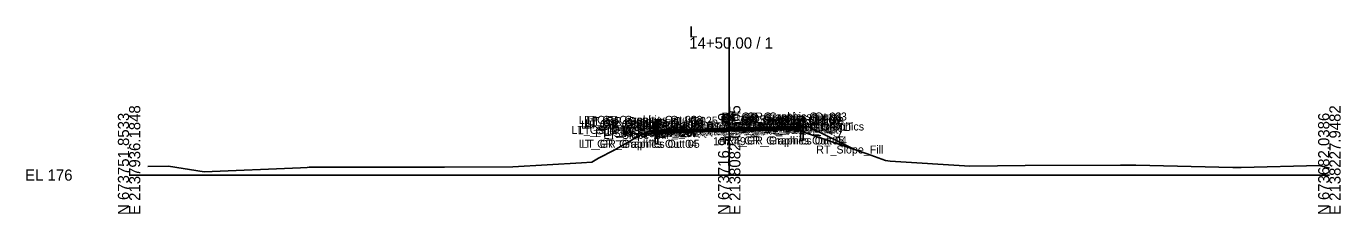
# Model space of a CAD drawing. Extents: x -26 to 5503, y -10 to 7033.
# Drawn here: x -25.7 to 302.8, y 5490.3 to 5537.3 of the extents above; entities that cross this region are included whole.
import ezdxf

# ---------------------------------------------------------------- set-up
doc = ezdxf.new("R2010")
doc.units = 0
for name, color, linetype in [('Default', 7, 'Continuous'), ('Exist Cross Section Cell', 7, 'Continuous'), ('Exist XS Center Line Elevation Label', 7, 'Continuous'), ('Exist XS Ground Line', 7, 'Continuous'), ('Prop CMT Guardrail Graphics', 7, 'Continuous'), ('Prop CMT Pvmt Course 1', 7, 'Continuous'), ('Prop CMT Pvmt Course 2', 7, 'Continuous'), ('Prop CMT Pvmt Course 3', 7, 'Continuous'), ('Prop CMT Pvmt Surface', 7, 'Continuous'), ('Prop CMT Pvmt Surface Overlay', 7, 'Continuous'), ('Prop CMT Pvmt Surface Shoulder', 7, 'Continuous'), ('Prop CMT Shld Paved Course 1', 7, 'Continuous'), ('Prop CMT Shld Paved Course 2', 7, 'Continuous'), ('Prop CMT Shld Paved Course 3', 7, 'Continuous'), ('Prop CMT Slope Grass', 7, 'Continuous'), ('Prop CMT Subgrade Earthwork', 7, 'Continuous'), ('Prop XS Earthwork Shape', 7, 'Continuous'), ('Prop XS EOT Tick Mark', 7, 'Continuous'), ('Prop XS SE Text', 7, 'Continuous'), ('Prop XS Side Slope Text', 7, 'Continuous')]:
    doc.layers.add(name, color=color, linetype=linetype)

msp = doc.modelspace()

# ---------------------------------------------------------------- linework, layer by layer
at = {"layer": 'Exist Cross Section Cell'}
for p, q in [((150, 5500), (150, 5534.48)), ((0, 5500), (150, 5500)), ((150, 5500), (300, 5500))]:
    msp.add_line(p, q, dxfattribs=at)
at = {"layer": 'Exist XS Ground Line'}
for p, q in [((121.21, 5506.22), (127.74, 5510)), ((127.74, 5510), (131.37, 5510.75)), ((131.37, 5510.75), (137.66, 5511.28)), ((137.66, 5511.28), (145.24, 5511.41)), ((145.24, 5511.41), (149.33, 5511.49)), ((149.33, 5511.49), (150, 5511.49)), ((150, 5511.49), (158.78, 5511.41)), ((158.78, 5511.41), (162.52, 5511.36)), ((162.52, 5511.36), (165.67, 5511.3)), ((165.67, 5511.3), (167.13, 5511.17)), ((167.13, 5511.17), (169.29, 5510.49)), ((169.29, 5510.49), (184.45, 5505.31)), ((117.35, 5504.23), (121.21, 5506.22)), ((95.92, 5502.03), (113.04, 5503.04)), ((113.04, 5503.04), (115.67, 5503.24)), ((115.67, 5503.24), (117.35, 5504.23)), ((184.45, 5505.31), (189.09, 5503.61)), ((189.09, 5503.61), (190.27, 5503.5)), ((190.27, 5503.5), (210.12, 5502.2)), ((4.7, 5502.18), (9.89, 5502.25)), ((9.89, 5502.25), (18.8, 5500.85)), ((18.8, 5500.85), (42.82, 5501.84)), ((42.82, 5501.84), (44.51, 5501.92)), ((44.51, 5501.92), (45.04, 5501.94)), ((45.04, 5501.94), (70.21, 5501.94)), ((70.21, 5501.94), (78.83, 5501.99)), ((78.83, 5501.99), (95.92, 5502.03)), ((210.12, 5502.2), (223.93, 5502.36)), ((223.93, 5502.36), (247.79, 5502.47)), ((247.79, 5502.47), (250.15, 5502.46)), ((250.15, 5502.46), (251.6, 5502.47)), ((251.6, 5502.47), (275.86, 5501.93)), ((275.86, 5501.93), (277.95, 5501.91)), ((277.95, 5501.91), (297.54, 5502.4)), ((297.54, 5502.4), (300, 5501.76))]:
    msp.add_line(p, q, dxfattribs=at)
at = {"layer": 'Prop CMT Guardrail Graphics'}
for points in [[(131.48, 5507.83), (131.48, 5513.83)], [(131.48, 5513.83), (132.81, 5513.83), (133.08, 5513.53)], [(133.08, 5512.95), (132.81, 5512.66), (132.15, 5512.66)], [(133.08, 5513.53), (132.81, 5513.24)], [(132.81, 5513.24), (133.08, 5512.95)], [(168.52, 5514.67), (167.19, 5514.67), (166.92, 5514.38)], [(166.92, 5514.38), (167.19, 5514.09)], [(167.19, 5514.09), (166.92, 5513.8)], [(166.92, 5513.8), (167.19, 5513.5), (167.85, 5513.5)], [(167.85, 5513.5), (167.85, 5508.67)], [(168.52, 5508.67), (168.52, 5514.67)], [(132.15, 5512.66), (132.15, 5507.83)], [(132.15, 5507.83), (131.48, 5507.83)], [(167.85, 5508.67), (168.52, 5508.67)]]:
    msp.add_lwpolyline(points, dxfattribs=at)
at = {"layer": 'Prop CMT Pvmt Course 1'}
for points in [[(150, 5511.75), (138, 5511.45)], [(138, 5511.2), (150, 5511.5)], [(138, 5511.45), (138, 5511.2)], [(150, 5511.75), (162, 5512.05)], [(162, 5511.8), (150, 5511.5)], [(150, 5511.62), (150, 5511.75)], [(150, 5511.62), (150, 5511.75)], [(150, 5511.5), (150, 5511.62), (150, 5511.62)], [(150, 5511.5), (150, 5511.62), (150, 5511.62)], [(162, 5512.05), (162, 5511.8)]]:
    msp.add_lwpolyline(points, dxfattribs=at)
at = {"layer": 'Prop CMT Pvmt Course 2'}
for points in [[(150, 5511.5), (138, 5511.2)], [(138, 5510.99), (150, 5511.29)], [(138, 5511.2), (138, 5510.99)], [(150, 5511.5), (162, 5511.8)], [(162, 5511.59), (150, 5511.29)], [(150, 5511.29), (150, 5511.5)], [(150, 5511.29), (150, 5511.5)], [(162, 5511.8), (162, 5511.59)]]:
    msp.add_lwpolyline(points, dxfattribs=at)
at = {"layer": 'Prop CMT Pvmt Course 3'}
for points in [[(150, 5511.29), (138, 5510.99)], [(138, 5510.99), (138, 5510.66)], [(138, 5510.66), (150, 5510.96)], [(150, 5511.29), (162, 5511.59)], [(150, 5510.96), (150, 5511.29)], [(150, 5510.96), (150, 5511.29)], [(162, 5511.26), (150, 5510.96)], [(162, 5511.59), (162, 5511.26)]]:
    msp.add_lwpolyline(points, dxfattribs=at)
at = {"layer": 'Prop CMT Pvmt Surface'}
for points in [[(150, 5511.75), (138, 5511.45)], [(150, 5511.75), (162, 5512.05)]]:
    msp.add_lwpolyline(points, dxfattribs=at)
at = {"layer": 'Prop CMT Pvmt Surface Overlay'}
for points in [[(150, 5511.75), (138, 5511.45)], [(150, 5511.75), (162, 5512.05)]]:
    msp.add_lwpolyline(points, dxfattribs=at)
at = {"layer": 'Prop CMT Pvmt Surface Shoulder'}
for points in [[(138, 5511.45), (133.09, 5511.33)], [(162, 5512.05), (166.91, 5512.17)]]:
    msp.add_lwpolyline(points, dxfattribs=at)
at = {"layer": 'Prop CMT Shld Paved Course 1'}
for points in [[(138, 5511.45), (133.09, 5511.33), (132.84, 5511.07)], [(132.84, 5511.07), (138, 5511.2)], [(138, 5511.2), (138, 5511.45)], [(162, 5512.05), (166.91, 5512.17), (167.15, 5511.93)], [(162, 5511.8), (162, 5512.05)], [(167.15, 5511.93), (162, 5511.8)]]:
    msp.add_lwpolyline(points, dxfattribs=at)
at = {"layer": 'Prop CMT Shld Paved Course 2'}
for points in [[(138, 5511.2), (132.84, 5511.07), (132.62, 5510.86)], [(132.62, 5510.86), (138, 5510.99)], [(138, 5510.99), (138, 5511.2)], [(162, 5511.8), (167.15, 5511.93), (167.35, 5511.72)], [(162, 5511.59), (162, 5511.8)], [(167.35, 5511.72), (162, 5511.59)]]:
    msp.add_lwpolyline(points, dxfattribs=at)
at = {"layer": 'Prop CMT Shld Paved Course 3'}
for points in [[(132.62, 5510.86), (132.28, 5510.51)], [(132.28, 5510.51), (138, 5510.66)], [(138, 5510.99), (132.62, 5510.86)], [(132.62, 5510.86), (132.62, 5510.86)], [(138, 5510.66), (138, 5510.99)], [(162, 5511.59), (167.35, 5511.72)], [(162, 5511.26), (162, 5511.59)], [(167.68, 5511.4), (162, 5511.26)], [(167.35, 5511.72), (167.35, 5511.72)], [(167.35, 5511.72), (167.68, 5511.4)]]:
    msp.add_lwpolyline(points, dxfattribs=at)
at = {"layer": 'Prop CMT Slope Grass'}
for points in [[(130.08, 5511.09), (128.04, 5510.07)], [(133.08, 5511.33), (130.08, 5511.09)], [(133.09, 5511.33), (133.08, 5511.33)], [(166.91, 5512.17), (166.92, 5512.17)], [(166.92, 5512.17), (169.92, 5512.07)], [(169.92, 5512.07), (181.28, 5506.4)]]:
    msp.add_lwpolyline(points, dxfattribs=at)
at = {"layer": 'Prop CMT Subgrade Earthwork'}
for points in [[(132.28, 5510.51), (131.59, 5511.21)], [(138, 5510.66), (132.28, 5510.51)], [(150, 5510.96), (138, 5510.66)], [(150, 5510.96), (162, 5511.26)], [(162, 5511.26), (167.68, 5511.4)], [(167.68, 5511.4), (168.4, 5512.12)]]:
    msp.add_lwpolyline(points, dxfattribs=at)
at = {"layer": 'Prop XS Earthwork Shape'}
for points in [[(131.99, 5510.81), (131.59, 5511.21), (130.08, 5511.09), (128.04, 5510.07), (131.37, 5510.75)], [(131.99, 5510.81), (137.66, 5511.28), (145.24, 5511.41), (149.33, 5511.49), (150, 5511.49), (158.78, 5511.41), (162.52, 5511.36), (164.57, 5511.32), (162, 5511.26), (150, 5510.96), (138, 5510.66), (132.28, 5510.51)], [(164.57, 5511.32), (165.67, 5511.3), (167.13, 5511.17), (169.29, 5510.49), (181.28, 5506.4), (169.92, 5512.07), (168.4, 5512.12), (167.68, 5511.4)]]:
    msp.add_lwpolyline(points, close=True, dxfattribs=at)
at = {"layer": 'Prop XS EOT Tick Mark'}
for points in [[(162, 5512.05), (162, 5513.05)], [(138, 5511.45), (138, 5512.45)]]:
    msp.add_lwpolyline(points, dxfattribs=at)

# ---------------------------------------------------------------- texts
at = {"layer": 'Default'}
for s, height, p in [('LT_GR_Graphics Out 03', 2, (112.38, 5512.83)), ('LT_GR_Graphics Out 06', 2, (113, 5511.66)), ('LT_GR_Graphics Out 02', 2, (113.71, 5512.83)), ('LT_GR_Graphics Out 09', 2, (113.71, 5512.24)), ('LT_GR_Graphics Out 07', 2, (113.71, 5511.66)), ('LT_GR_Graphics Out 08', 2, (113.98, 5511.95)), ('LT_GR_Graphics Out 01', 2, (114.55, 5512.53)), ('LT_TM_OEOT', 2, (128.94, 5511.45)), ('RT_GS_OS_GR_Face_Graphics', 2, (144.33, 5511.17)), ('PV1_PGL', 2, (144.47, 5510.75)), ('RT_GR_Graphics Out 08', 2, (147.77, 5512.8)), ('RT_GR_Graphics Out 02', 2, (148.04, 5513.67)), ('RT_GR_Graphics Out 09', 2, (148.04, 5513.09)), ('RT_GR_Graphics Out 07', 2, (148.04, 5512.5)), ('RT_GR_Graphics Out 01', 2, (148.33, 5513.38)), ('RT_GR_Graphics Out 06', 2, (148.66, 5512.5)), ('RT_Sub_Trench_Out_DLT', 2, (148.92, 5511.12)), ('RT_GR_Graphics Out 03', 2, (149.37, 5513.67)), ('RT_PV2_OEOT', 2, (152.13, 5510.8)), ('RT_PV1_OEOT', 2, (152.69, 5511.05)), ('RT_TM_OEOT', 2, (152.9, 5512.05)), ('RT_PS3_Shelf_Out', 2, (153.29, 5510.72)), ('RT_PS2_OEOP', 2, (157.34, 5510.93)), ('RT_PS1_OEOP', 2, (157.66, 5511.17)), ('RT_GS_OS_CTL', 2, (159.24, 5511.07)), ('LT_GS_OS_GR_Face_Graphics', 2, (110.54, 5510.33)), ('LT_Sub_Trench_Out_DLT', 2, (112.16, 5510.21)), ('LT_Sub_Trench_Out', 2, (116.49, 5509.51)), ('LT_Slope_Fill', 2, (118.56, 5509.07)), ('LT_PS3_Shelf_Out', 2, (118.61, 5509.86)), ('LT_GS_OS_CTL', 2, (119.45, 5510.09)), ('LT_PS3_OEOP', 2, (122.86, 5509.86)), ('LT_PS2_OEOP', 2, (123.07, 5510.07)), ('LT_PS1_OEOP', 2, (123.9, 5510.33)), ('LT_Sub_OEOT', 2, (128.08, 5509.66)), ('LT_PV2_OEOT', 2, (128.17, 5510.2)), ('LT_PV3_OEOT', 2, (128.17, 5509.99)), ('LT_PV1_OEOT', 2, (128.74, 5510.45)), ('RT_PV1_OEEOP_W', 2, (137.94, 5510.62)), ('LT_PV1_OEEOP_W', 2, (137.98, 5510.62)), ('RT_Sub_OEEOP', 2, (139.17, 5509.96)), ('LT_Sub_OEEOP', 2, (139.21, 5509.96)), ('RT_PV2_OEEOP', 2, (139.26, 5510.5)), ('RT_PV3_OEEOP', 2, (139.26, 5510.29)), ('LT_PV2_OEEOP', 2, (139.31, 5510.5)), ('LT_PV3_OEEOP', 2, (139.31, 5510.29)), ('PV1_PGL_W', 2, (142.58, 5510.62)), ('RT_GR_Graphics Out 05', 2, (148.7, 5507.67)), ('RT_GR_Graphics Out 04', 2, (149.37, 5507.67)), ('RT_Sub_Trench_Out', 2, (151.84, 5510.4)), ('RT_Sub_OEOT', 2, (152.03, 5510.26)), ('RT_PV3_OEOT', 2, (152.13, 5510.59)), ('RT_PS3_OEOP', 2, (157.54, 5510.72)), ('LT_GR_Graphics Out 04', 2, (112.38, 5506.83)), ('LT_GR_Graphics Out 05', 2, (113.04, 5506.83)), ('RT_Slope_Fill', 2, (171.75, 5505.4)), ('-', 0.0001, (0, 5500))]:
    msp.add_text(s, height=height, dxfattribs=at).set_placement(p)
at = {"layer": 'Exist Cross Section Cell'}
for s, p in [('L', (140, 5534.48)), ('14+50.00 / 1', (140, 5531.68)), ('EL 176', (-26, 5498.6))]:
    msp.add_text(s, height=2.8, dxfattribs=at).set_placement(p)
for s, p in [('E 2137936.1848', (2.8, 5490)), ('E 2138082.0665', (152.8, 5490)), ('E 2138227.9482', (302.8, 5490)), ('N 673751.8533', (0, 5490)), ('N 673716.9459', (150, 5490)), ('N 673682.0386', (300, 5490))]:
    msp.add_text(s, height=2.8, rotation=90, dxfattribs=at).set_placement(p)
at = {"layer": 'Exist XS Center Line Elevation Label'}
msp.add_text('187.49', height=2, dxfattribs=at).set_placement((145.97, 5507.49))
at = {"layer": 'Prop XS SE Text'}
for p in [(140.48, 5512.51), (152.48, 5512.81)]:
    msp.add_text('0.025', height=2, rotation=1.4321, dxfattribs=at).set_placement(p)
at = {"layer": 'Prop XS Side Slope Text'}
for rotation, p in [(26.5268, (127.29, 5510.53)), (333.4732, (174.5, 5510.62))]:
    msp.add_text('2:1', height=2, rotation=rotation, dxfattribs=at).set_placement(p)

doc.saveas('drawing.dxf')
